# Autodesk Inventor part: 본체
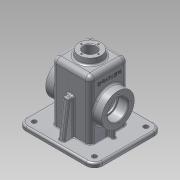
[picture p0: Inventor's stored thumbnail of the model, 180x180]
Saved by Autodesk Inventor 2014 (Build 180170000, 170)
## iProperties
Created: 2016-08
Part Number: 본체
Material: 알루미늄 6061
Document SubType Name: Modeling
Designer: user
Density: 2.71 g/cm^3
Appearance: 알루미늄 - 평지
Mass: 796.088 g
Surface Area: 911.213 cm^2
Volume: 293.76 cm^3
Author: user
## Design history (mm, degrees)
sketch "스케치1"
  geometry: L1 (0, 0)-(130, 0); L2 (130, 0)-(130, 115); L3 (130, 115)-(0, 115); L4 (0, 115)-(0, 0)
  constraints: 8 end point, 2 parallel, 1 horizontal, 1 perpendicular
  dimensions: "d0" = 130 distance of L3.end L2.end; "d1" = 115 distance of L2.end L1.end
extrude "돌출1" new body sketch "스케치1" distance "d2" = 7; taper "d3" = 0 deg
sketch "스케치2"
  geometry: L1 (32.5, 25)-(97.5, 25); L2 (97.5, 25)-(97.5, 90); L3 (97.5, 90)-(32.5, 90); L4 (32.5, 90)-(32.5, 25); L5 (130, 115)-(0, 115) reference; L6 (0, 115)-(0, 0) reference
  constraints: 8 end point, 2 parallel, 1 horizontal, 1 perpendicular
  dimensions: "d4" = 65 distance of L3.end L2.end; "d5" = 65 distance of L2.end L1.end; "d6" = 25 distance between parallel lines of L5 L3; "d7" = 32.5 distance between parallel lines of L6 L4
extrude "돌출2" join sketch "스케치2" distance "d8" = 100; taper "d9" = 0 deg
fillet "모깎기1" dims "d10" = 14
sketch "스케치3"
  geometry: L1 (32.5, 25)-(97.5, 25) reference; L2 (97.5, 25)-(97.5, 90) reference; L3 (97.5, 90)-(32.5, 90) reference; L4 (32.5, 90)-(32.5, 25) reference; L5 (97.5, 90)-(32.5, 90) reference; L6 (32.5, 90)-(32.5, 25) reference; C1 r 20 at (65, 57.5); 3 further points
  constraints: 2 midpoint, 1 centre point, 1 horizontal alignment, 1 vertical alignment
  dimensions: "d11" = 40 diameter of C1
extrude "돌출3" join sketch "스케치3" distance "d12" = 10; taper "d13" = 0 deg
sketch "스케치4"
  geometry: L1 (0, 0)-(0, 65) reference; L2 (0, 0)-(100, 0) reference; L3 (100, 65)-(100, 0) reference; L4 (0, 65)-(100, 65) reference; L5 (0, 76)-(0, -11) reference; L6 (-7, 76)-(-7, -11) reference; C1 r 27.5 at (45, 32.5); 2 further points
  constraints: 1 centre point, 1 horizontal alignment, 1 midpoint
  dimensions: "d14" = 55 diameter of C1; "d15" = 52 distance from line of L6 C1.centre
extrude "돌출4" join sketch "스케치4" distance "d16" = 15; taper "d17" = 0 deg
sketch "스케치5"
  geometry: L1 (7, -11)-(7, 76) reference; C1 r 27.5 at (-45, 32.5); 2 further points
  constraints: 1 centre point, 1 horizontal alignment, 1 midpoint
  dimensions: "d18" = 55 diameter of C1; "d19" = 52 distance from line of L1 C1.centre
extrude "돌출5" join sketch "스케치5" distance "d20" = 15; taper "d21" = 0 deg
sketch "스케치7"
  geometry: L1 (-37.5, 30)-(-92.5, 30); L2 (-92.5, 30)-(-92.5, 85); L3 (-92.5, 85)-(-37.5, 85); L4 (-37.5, 85)-(-37.5, 30); L5 (-14, 0)-(-116, 0) reference; L6 (0, 101)-(0, 14) reference; 5 further points
  constraints: 8 end point, 4 midpoint, 2 parallel, 1 horizontal, 1 horizontal alignment, 1 perpendicular, 1 vertical alignment
  dimensions: "d22" = 55 distance of L2.end L3.end; "d23" = 55 distance of L1.end L2.end
extrude "돌출6" cut sketch "스케치7" distance "d24" = 102; taper "d25" = 0 deg
sketch "스케치8"
  geometry: L1 (37.5, 85)-(37.5, 30) reference; L2 (37.5, 30)-(92.5, 30) reference; L3 (92.5, 30)-(92.5, 85) reference; L4 (92.5, 85)-(37.5, 85) reference; L5 (130, 14)-(130, 101) reference; L6 (14, 0)-(116, 0) reference; L7 (0, 101)-(0, 14) reference; L8 (116, 115)-(14, 115) reference; L9 (22.5, 60.5)-(37.5, 60.5); L10 (37.5, 60.5)-(37.5, 54.5); L11 (37.5, 54.5)-(22.5, 54.5); L12 (22.5, 54.5)-(22.5, 60.5); L13 (92.5, 60.5)-(107.5, 60.5); L14 (107.5, 60.5)-(107.5, 54.5); L15 (107.5, 54.5)-(92.5, 54.5); L16 (92.5, 54.5)-(92.5, 60.5); A1 r 14 centre (116, 101) between (130, 101) and (116, 115) reference; A2 r 14 centre (116, 14) between (116, 0) and (130, 14) reference; A3 r 14 centre (14, 14) between (0, 14) and (14, 0) reference; A4 r 14 centre (14, 101) between (14, 115) and (0, 101) reference; 5 further points
  constraints: 16 end point, 4 midpoint, 4 parallel, 2 horizontal, 2 horizontal alignment, 2 perpendicular, 2 point on line
  dimensions: "d26" = 15 distance of L10.end L11.end; "d27" = 15 distance of L14.end L15.end; "d28" = 6 distance of L11.end L9.start; "d29" = 6 distance of L13.end L14.end
extrude "돌출7" join sketch "스케치8" stored distance "d30" = 105; taper "d31" = 0 deg
sketch "스케치9"
  geometry: L1 (37.5, 85)-(37.5, 30) reference; L2 (37.5, 30)-(92.5, 30) reference; L3 (92.5, 30)-(92.5, 85) reference; L4 (92.5, 85)-(37.5, 85) reference; L5 (130, 14)-(130, 101) reference; L6 (14, 0)-(116, 0) reference; L7 (0, 101)-(0, 14) reference; L8 (116, 115)-(14, 115) reference; L9 (70, 8)-(60, 8); L10 (60, 8)-(60, 30); L11 (60, 30)-(70, 30); L12 (70, 30)-(70, 8); L13 (70, 85)-(60, 85); L14 (60, 85)-(60, 107); L15 (60, 107)-(70, 107); L16 (70, 107)-(70, 85); A1 r 14 centre (116, 101) between (130, 101) and (116, 115) reference; A2 r 14 centre (116, 14) between (116, 0) and (130, 14) reference; A3 r 14 centre (14, 14) between (0, 14) and (14, 0) reference; A4 r 14 centre (14, 101) between (14, 115) and (0, 101) reference; 5 further points
  constraints: 16 end point, 4 midpoint, 4 parallel, 2 horizontal, 2 perpendicular, 2 point on line, 2 vertical alignment
  dimensions: "d32" = 8 distance between parallel lines of L9 L6; "d33" = 8 distance between parallel lines of L8 L15; "d34" = 10 distance of L9.start L9.end; "d35" = 10 distance of L14.end L15.end
extrude "돌출8" join sketch "스케치9" distance "d36" = 60; taper "d37" = 0 deg
feature "면 기울기1" dims angle "d38" = 8 deg
fillet "모깎기2" dims "d39" = 8
fillet "모깎기3" dims "d40" = 8
hole "구멍1" diameter "d43" = 21; stored, may be unused: countersink angle "d47" = 90 deg, drill point angle "d49" = 118 deg; dims "d44" = 6, "d45" = 4, "d46" = 2, "d48" = 8, "d50" = 10, "d51" = 10
hole "구멍2" diameter "d54" = 30; stored, may be unused: countersink angle "d58" = 90 deg, drill point angle "d60" = 118 deg; dims "d52" = 10, "d53" = 10, "d55" = 6, "d56" = 4, "d57" = 2, "d59" = 8
hole "구멍3" diameter "d63" = 35; stored, may be unused: countersink angle "d67" = 90 deg, drill point angle "d69" = 0 deg; dims "d64" = 6, "d65" = 4, "d66" = 2, "d68" = 17, "d79" = 10, "d80" = 10
hole "구멍4" diameter "d72" = 35; stored, may be unused: countersink angle "d76" = 90 deg, drill point angle "d78" = 0 deg; dims "d70" = 10, "d71" = 10, "d73" = 6, "d74" = 4, "d75" = 2, "d77" = 17
fillet "모깎기4" dims "d81" = 0.3
fillet "모깎기5" dims "d82" = 3
fillet "모깎기6" dims "d83" = 3
fillet "모깎기7" dims "d84" = 3
fillet "모깎기8" dims "d85" = 3
feature "면 기울기2" dims angle "d86" = 7 deg
fillet "모깎기9" dims "d87" = 3
fillet "모깎기10" dims "d88" = 3
fillet "모깎기11" dims "d89" = 3
fillet "모깎기12" dims "d90" = 1
sketch "스케치10"
  geometry: L1 (-14, 5)-(-116, 5); L2 (-125, 14)-(-125, 101); L3 (-116, 110)-(-14, 110); L4 (-5, 101)-(-5, 14); L5 (-37.5, 82)-(-37.5, 33) reference; L6 (-40.5, 30)-(-89.5, 30) reference; L7 (-92.5, 33)-(-92.5, 82) reference; L8 (-89.5, 85)-(-40.5, 85) reference; L9 (-130, 14)-(-130, 101) reference; L10 (-14, 0)-(-116, 0) reference; L11 (0, 101)-(0, 14) reference; L12 (-116, 115)-(-14, 115) reference; L13 (-14, 0)-(-116, 0) reference; A1 r 3 centre (-40.5, 33) between (-40.5, 30) and (-37.5, 33) reference; A2 r 3 centre (-89.5, 33) between (-92.5, 33) and (-89.5, 30) reference; A3 r 3 centre (-89.5, 82) between (-89.5, 85) and (-92.5, 82) reference; A4 r 3 centre (-40.5, 82) between (-37.5, 82) and (-40.5, 85) reference; A5 r 14 centre (-116, 101) between (-116, 115) and (-130, 101) reference; A6 r 14 centre (-116, 14) between (-130, 14) and (-116, 0) reference; A7 r 14 centre (-14, 14) between (-14, 0) and (0, 14) reference; A8 r 14 centre (-14, 101) between (0, 101) and (-14, 115) reference; A9 r 9 centre (-14, 14) between (-14, 5) and (-5, 14); A10 r 9 centre (-14, 101) between (-5, 101) and (-14, 110); A11 r 9 centre (-116, 101) between (-116, 110) and (-125, 101); A12 r 9 centre (-116, 14) between (-125, 14) and (-116, 5); 8 further points
  constraints: 8 end point, 8 point on circle, 8 tangent, 6 point on line, 4 centre point, 4 midpoint, 2 equal radius, 2 parallel, 1 horizontal, 1 horizontal alignment, 1 perpendicular, 1 vertical alignment
  dimensions: "d91" = 120 distance of point (-125, 110) point (-5, 110); "d92" = 105 distance of point (-125, 5) point (-125, 110); "d93" = 9 radius of A9; "d94" = 9 radius of A10
extrude "돌출9" join sketch "스케치10" distance "d95" = 3; taper "d96" = 0 deg
fillet "모깎기13" dims "d97" = 3
sketch "스케치11"
  geometry: L1 (-40.5, 30)-(-89.5, 30) reference; L2 (-92.5, 33)-(-92.5, 82) reference; L3 (-89.5, 85)-(-40.5, 85) reference; L4 (-37.5, 82)-(-37.5, 33) reference; L5 (-5, 14)-(-5, 101) reference; L6 (-14, 110)-(-116, 110) reference; L7 (-125, 101)-(-125, 14) reference; L8 (-116, 5)-(-14, 5) reference; C1 r 4 at (-14, 14); C2 r 4 at (-116, 14); C3 r 4 at (-116, 101); C4 r 4 at (-14, 101); A1 r 3 centre (-40.5, 33) between (-40.5, 30) and (-37.5, 33) reference; A2 r 3 centre (-89.5, 33) between (-92.5, 33) and (-89.5, 30) reference; A3 r 3 centre (-89.5, 82) between (-89.5, 85) and (-92.5, 82) reference; A4 r 3 centre (-40.5, 82) between (-37.5, 82) and (-40.5, 85) reference; A5 r 9 centre (-14, 101) between (-5, 101) and (-14, 110) reference; A6 r 9 centre (-116, 101) between (-116, 110) and (-125, 101) reference; A7 r 9 centre (-116, 14) between (-125, 14) and (-116, 5) reference; A8 r 9 centre (-14, 14) between (-14, 5) and (-5, 14) reference; 1 further point
  constraints: 4 centre point, 4 coincident
  dimensions: "d98" = 8 diameter of C1; "d99" = 8 diameter of C2; "d100" = 8 diameter of C3; "d101" = 8 diameter of C4
extrude "돌출10" cut sketch "스케치11" distance "d102" = 10; taper "d103" = 0 deg
chamfer "모따기1" distance "d104" = 1; stored, may be unused: second distance "d105" = 2, angle "d106" = 45 deg
sketch "스케치12"
  geometry: L1 (-55, -43.5)-(-55, 43.5) reference; L2 (47, 24.5)-(47, -24.5) reference; L3 (47, 32.5)-(-44, 32.5) reference; L4 (-44, -32.5)-(47, -32.5) reference; L5 (-52, 43.5)-(-52, -43.5) reference; A1 r 21 centre (0, 0) between (21, 0) and (0, -21); 2 further points
  constraints: 4 point on circle, 1 centre point
  dimensions: "d107" = 42 diameter of A1; "d145" = 55 distance from line of L1 A1.centre; "d146" = 26 distance from line of L2 A1.start; "d147" = 11.5 distance from line of L3 point (0, 21); "d148" = 11.5 distance from line of L4 A1.end; "d149" = 31 distance from line of L5 point (-21, 0); "d150" = 32.5 distance from line of L3 A1.centre
hole "구멍5" sketch "스케치12" at (21, 0), (0, -21), (-21, 0), (0, 21) diameter "d108" = 3.242; stored, may be unused: countersink angle "d112" = 90 deg, drill point angle "d114" = 118 deg; dims "d109" = 8, "d110" = 4, "d111" = 2, "d113" = 10
sketch "스케치13"
  geometry: L1 (55, 43.5)-(55, -43.5) reference; L2 (-47, -24.5)-(-47, 24.5) reference; L3 (-47, -32.5)-(44, -32.5) reference; L4 (-47, 24.5)-(-18.166, 24.5) reference; A1 r 21 centre (0, 0) between (-21, 0) and (0, 21); 2 further points
  constraints: 4 point on circle, 1 centre point
  dimensions: "d115" = 42 diameter of A1; "d151" = 55 distance from line of L1 A1.centre; "d152" = 26 distance from line of L2 A1.start; "d153" = 11.5 distance from line of L3 point (0, -21); "d154" = 3.5 distance from line of L4 A1.end; "d155" = 34 distance from line of point (21, 0) L1; "d156" = 24.5 distance from line of point (21, 0) L4
hole "구멍6" sketch "스케치13" at (-21, 0), (0, 21), (21, 0), (0, -21) diameter "d121" = 3.242; stored, may be unused: countersink angle "d125" = 90 deg, drill point angle "d127" = 118 deg; dims "d122" = 8, "d123" = 4, "d124" = 2, "d126" = 10
sketch "스케치14"
  geometry: A1 r 14.5 centre (0, 0) between (-14.5, 0) and (14.5, 0); 3 further points
  constraints: 4 point on circle, 1 centre point
  dimensions: "d133" = 29 diameter of A1
hole "구멍7" sketch "스케치14" at (-14.5, 0), (14.5, 0), (0, 14.5), (0, -14.5) diameter "d134" = 2.459; stored, may be unused: countersink angle "d138" = 90 deg, drill point angle "d140" = 118 deg; dims "d135" = 7, "d136" = 4, "d137" = 2, "d139" = 9
sketch "스케치15"
  geometry: L1 (0, -8)-(91, -8) reference; L2 (-18, 43.272)-(-18, 5.728) reference; 2 further points
  constraints: 1 other
  dimensions: "d141" = 32.5 distance from line of L1 point (8, 24.5); "d142" = 26 distance from line of L2 point (8, 24.5)
feature "엠보싱1" sketch "스케치15" dims "d143" = 0.5, "d144" = 0
node "솔리드1"
node "투영된 루프1"
node "투영된 루프2"
node "투영된 루프3"
node "투영된 루프4"
node "투영된 루프5"
node "투영된 루프6"
